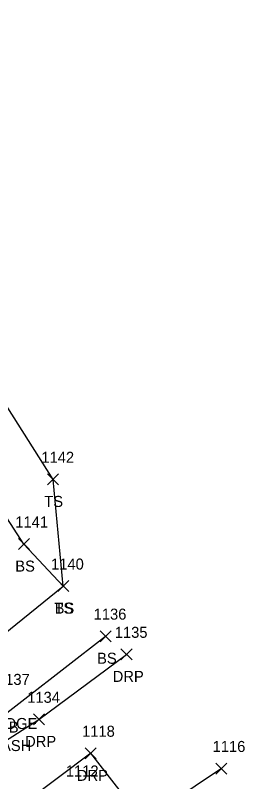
# Model space of a CAD drawing. Extents: x 1501299 to 1502485, y 381423 to 383765.
# Drawn here: x 1501888.1 to 1501929.8, y 382944 to 383083.1 of the extents above; entities that cross this region are included whole.
import ezdxf

# ---------------------------------------------------------------- set-up
doc = ezdxf.new("R2010")
doc.units = 0
for name, color, linetype in [('L_A', 7, 'Continuous'), ('L_C', 7, 'Continuous'), ('L_I', 7, 'Continuous'), ('L_TIC', 7, 'Continuous'), ('LELB', 7, 'Continuous'), ('R_A', 7, 'Continuous'), ('R_I', 7, 'Continuous'), ('R_TIC', 7, 'Continuous'), ('RDP', 7, 'Continuous')]:
    doc.layers.add(name, color=color, linetype=linetype)

msp = doc.modelspace()

# ---------------------------------------------------------------- linework, layer by layer
at = {"layer": 'L_TIC'}
for points in [[(1501893.94, 382997.89), (1501895.94, 382999.89)], [(1501895.94, 382997.89), (1501893.94, 382999.89)], [(1501888.64, 382986.15), (1501890.64, 382988.15)], [(1501890.64, 382986.15), (1501888.64, 382988.15)], [(1501895.79, 382978.52), (1501897.79, 382980.52)], [(1501897.79, 382978.52), (1501895.79, 382980.52)], [(1501895.79, 382978.52), (1501897.79, 382980.52)], [(1501897.79, 382978.52), (1501895.79, 382980.52)], [(1501903.5, 382969.43), (1501905.5, 382971.43)], [(1501905.5, 382969.43), (1501903.5, 382971.43)]]:
    msp.add_lwpolyline(points, dxfattribs=at)
at = {"layer": 'LELB'}
for points in [[(1501875.5, 382965.59), (1501878.56, 382964.8), (1501896.79, 382979.52), (1501894.94, 382998.89), (1501871.36, 383036.08), (1501850.54, 383070.75), (1501846.45, 383083.09)], [(1501896.79, 382979.52), (1501889.64, 382987.15), (1501882.83, 382997.53), (1501862.66, 383032.28), (1501842.54, 383064.76), (1501837.38, 383078.16)], [(1501872.66, 382953.64), (1501882.44, 382953.4), (1501904.5, 382970.43)]]:
    msp.add_lwpolyline(points, dxfattribs=at)
at = {"layer": 'R_TIC'}
for points in [[(1501907.29, 382966.13), (1501909.29, 382968.13)], [(1501909.29, 382966.13), (1501907.29, 382968.13)], [(1501891.37, 382954.34), (1501893.37, 382956.34)], [(1501893.37, 382954.34), (1501891.37, 382956.34)], [(1501900.78, 382948.18), (1501902.78, 382950.18)], [(1501902.78, 382948.18), (1501900.78, 382950.18)], [(1501924.55, 382945.42), (1501926.55, 382947.42)], [(1501926.55, 382945.42), (1501924.55, 382947.42)]]:
    msp.add_lwpolyline(points, dxfattribs=at)
at = {"layer": 'RDP'}
for points in [[(1501858.07, 382956.49), (1501858.95, 382957.67), (1501867.27, 382944.54), (1501869.91, 382942.93), (1501876.8, 382945.41), (1501892.37, 382955.34), (1501908.29, 382967.13)], [(1501925.55, 382946.42), (1501911.35, 382936.93), (1501901.78, 382949.18), (1501884.35, 382936.17), (1501878.9, 382927.17), (1501878.51, 382922.49)]]:
    msp.add_lwpolyline(points, dxfattribs=at)

# ---------------------------------------------------------------- texts
at = {"layer": 'L_A'}
for s, p in [('TS', (1501893.35, 382993.89)), ('BS', (1501888.08, 382982.15)), ('TS', (1501895.2, 382974.52)), ('BS', (1501895.23, 382974.52)), ('BS', (1501902.94, 382965.43)), ('HEDGE', (1501882.59, 382953.59))]:
    msp.add_text(s, height=2, dxfattribs=at).set_placement(p)
at = {"layer": 'L_C'}
for s, p in [('RHODENDRUB', (1501869.52, 382952.94)), ('S.ASH', (1501882.96, 382949.59))]:
    msp.add_text(s, height=2, dxfattribs=at).set_placement(p)
at = {"layer": 'L_I'}
for s, p in [('1142', (1501892.82, 383001.89)), ('1141', (1501888.08, 382990.15)), ('1140', (1501894.58, 382982.52)), ('1140', (1501894.58, 382982.52)), ('1136', (1501902.32, 382973.43)), ('1137', (1501884.76, 382961.59)), ('1112', (1501897.26, 382944.97)), ('1112', (1501897.26, 382944.97))]:
    msp.add_text(s, height=2, dxfattribs=at).set_placement(p)
at = {"layer": 'R_A'}
for p in [(1501905.78, 382962.13), (1501889.86, 382950.34), (1501899.27, 382944.18)]:
    msp.add_text('DRP', height=2, dxfattribs=at).set_placement(p)
at = {"layer": 'R_I'}
for s, p in [('1135', (1501906.16, 382970.13)), ('1134', (1501890.25, 382958.34)), ('1118', (1501900.22, 382952.18)), ('1116', (1501923.94, 382949.42))]:
    msp.add_text(s, height=2, dxfattribs=at).set_placement(p)

doc.saveas('drawing.dxf')
